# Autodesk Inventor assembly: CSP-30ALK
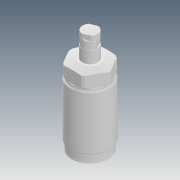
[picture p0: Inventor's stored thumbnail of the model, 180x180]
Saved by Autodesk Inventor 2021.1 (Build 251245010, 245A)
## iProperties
Created: 2019-01
Part Number: CSP-30ALK
Description: STEP AP203
Document SubType Name: Assembly
Designer: user
Title: CSP-030-K×é×°Í¼£¨ÉÏÉý×´Ì¬£©.STEP
Revision Number: ÈÎºÎ
Sending System: SolidWorks 2014
Preprocessor: SwSTEP 2.0
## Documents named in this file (4)
- D:\Vault_2016\Projekty\Clamptek\Hydraulic\CSP-P-K\CSP-30KP\Inventor\CSP-30ALK\CSP-30ALK.iam
- D:\Vault_2016\Projekty\Clamptek\Hydraulic\CSP-P-K\CSP-30KP\Inventor\CSP-30ALK\CSP-030-K±¾Ìå£¨ÉÏÉý£©.ipt
- D:\Vault_2016\Projekty\Clamptek\Hydraulic\CSP-P-K\CSP-30KP\Inventor\CSP-30ALK\CSP-030»îÈû¸Ë.ipt
- D:\Vault_2016\Projekty\Clamptek\Hydraulic\CSP-P-K\CSP-30KP\Inventor\CSP-30ALK\CSP-030Ô²Í·ÂÝË¨.ipt
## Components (3 placed, 3 different names)
1. CSP-030-K±¾Ìå£¨ÉÏÉý£©_1
2. CSP-030»îÈû¸Ë_2
3. CSP-030Ô²Í·ÂÝË¨_3
